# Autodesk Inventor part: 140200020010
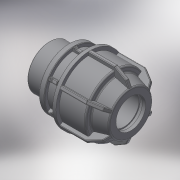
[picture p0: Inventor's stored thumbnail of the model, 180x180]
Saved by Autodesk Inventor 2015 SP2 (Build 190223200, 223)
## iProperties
Created: 2017-08
Part Number: 140200020010
Material: Generic
Description: PLASSON L.14 MALE ADAPTOR (SILVER) 20-1''
Document SubType Name: Modeling
Designer: KIM
Density: 1 g/cm^3
Appearance: Default
Author: KIM
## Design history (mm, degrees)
derived "140200.ipt"
feature "Solid1::140200.ipt"
tag "TaggingFeature1"
body "Solid1"
other parameters: "d4" = 15 deg, "d5" = 33, "d6" = 10.89, "d16" = 20.4, "d17" = 2.5, "d18" = 77, "d19" = 5.4, "d21" = 5.4, "d22" = 39.8988, "d24" = 2.5, "d25" = 45, "d26" = 37.5, "d27" = 2.5, "d28" = 135 deg, "d29" = 1.5, "d31" = 1, "d44" = 0.4, "d45" = 0.6, "d46" = 150 deg, "d49" = 2.5, "d50" = 0, "d51" = 1.5, "d52" = 1, "d53" = 45 deg, "d54" = 21, "d55" = 8.4, "d56" = 2.5, "d57" = 0, "d58" = 0.6, "d59" = 0.4, "d61" = 360 deg, "d63" = 33.249, "d64" = 16, "d65" = 18, "d66" = 44.88615, "R_" = 33.249, "H_" = 77, "l_2" = 18
